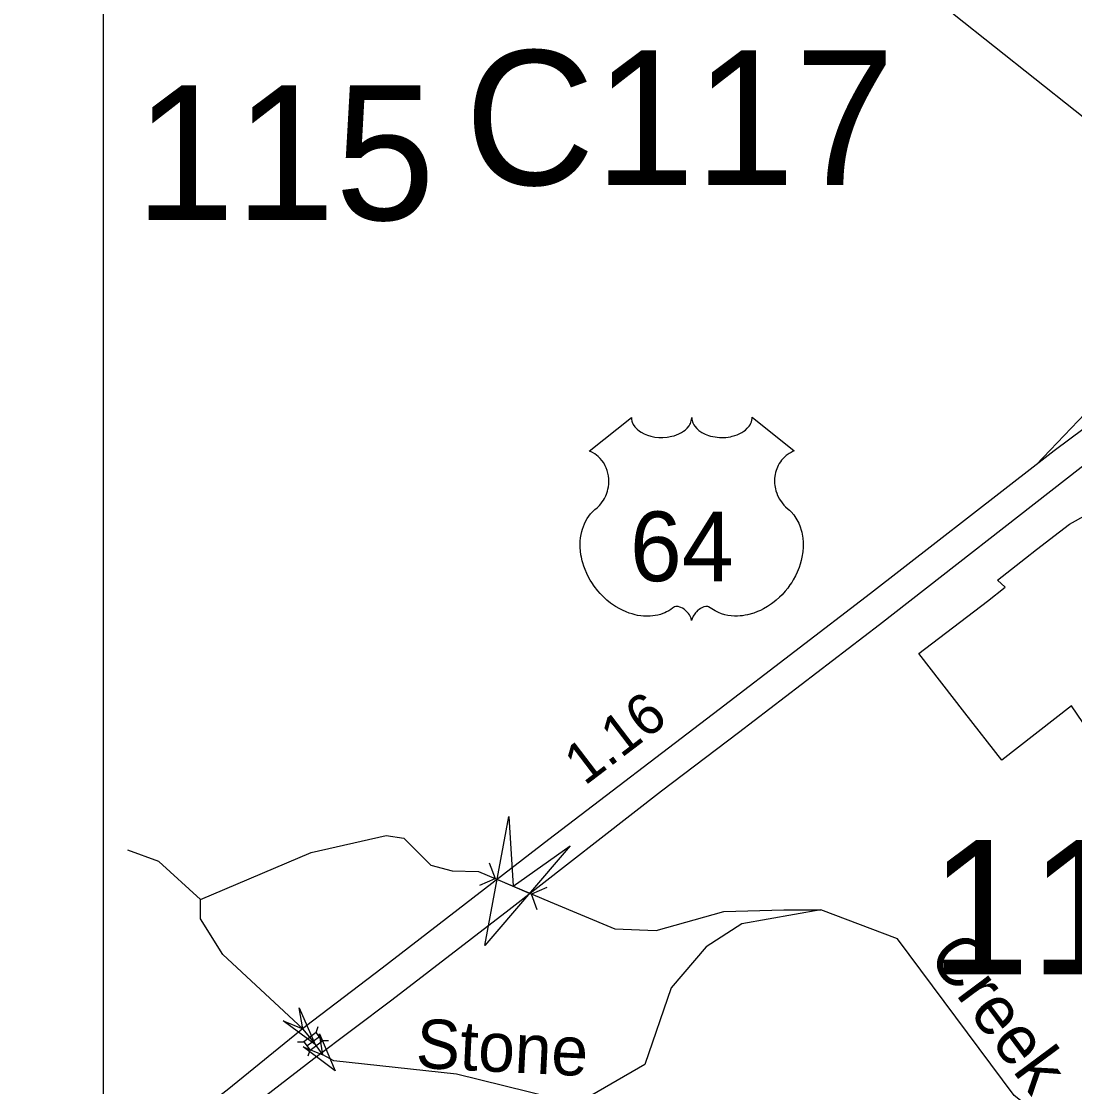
# Model space of a CAD drawing. Extents: x 2220236 to 2384410, y 720751 to 894131.
# Drawn here: x 2299383 to 2302594, y 810821 to 814069 of the extents above; entities that cross this region are included whole.
import ezdxf

# ---------------------------------------------------------------- set-up
doc = ezdxf.new("R2010")
doc.units = 0
doc.layers.add('Default', color=7, linetype='Continuous')

msp = doc.modelspace()

# ---------------------------------------------------------------- linework, layer by layer
at = {"layer": 'Default'}
for p, q in [((2300809.5, 811503.4), (2300827.1, 811455.8)), ((2300780.5, 811435.7), (2300827.1, 811455.8)), ((2300827.1, 811455.8), (2300938.2, 811408.1)), ((2300984.8, 811428.2), (2300938.2, 811408.1)), ((2300955.7, 811360.4), (2300938.2, 811408.1)), ((2300282.1, 810986.2), (2300287.7, 811004.2)), ((2300225.3, 810957.1), (2300244.2, 810957.6)), ((2300253.7, 810945), (2300291.6, 810973.6)), ((2300300.9, 810961.2), (2300319.8, 810961.8)), ((2300257.6, 810914.4), (2300263.2, 810932.4))]:
    msp.add_line(p, q, dxfattribs=at)
for points in [[(2299633.7, 818158.8), (2318694.1, 818158.8), (2318694.1, 801601.3), (2299633.7, 801601.3), (2299633.7, 818158.8)], [(2303026.8, 813458), (2302964.3, 813503.2), (2302226.3, 814089.1), (2301901.5, 814371.3), (2301400.9, 814817.8)], [(2303026.8, 813458), (2302895.1, 813248.5), (2302668.7, 812918.3), (2302476.3, 812716.3)], [(2303219, 813282), (2302940.9, 813063.9), (2302531.8, 812759.3), (2302476.3, 812716.3)], [(2300274.8, 810906.3), (2300512.6, 811085.2), (2300870.2, 811361.4), (2301334.3, 811722.6), (2301569.6, 811900.6), (2301999.5, 812230.1), (2302613.3, 812709.4), (2302643.9, 812732.1)], [(2302476.3, 812716.3), (2301971.3, 812324.1), (2301510.5, 811970.5), (2300990.8, 811574.4), (2300482.7, 811182.5), (2300249.8, 811004.5)], [(2302618.5, 811931.2), (2302584, 811982.1), (2302371.8, 811816.6), (2302259.2, 811961.1), (2302118.8, 812141.6), (2302327.8, 812301.6), (2302382.5, 812343.6), (2302358.5, 812364.8), (2302444.5, 812432), (2302478, 812458.2), (2302547.5, 812512.8), (2302577.8, 812536.4), (2302718, 812613.9)], [(2302618.5, 811931.2), (2302584, 811982.1), (2302371.8, 811816.6), (2302259.2, 811961.1), (2302118.8, 812141.6), (2302327.8, 812301.6), (2302382.5, 812343.6), (2302358.5, 812364.8), (2302444.5, 812432), (2302478, 812458.2), (2302547.5, 812512.8), (2302577.8, 812536.4), (2302718, 812613.9)], [(2299929.2, 811391.2), (2300267, 811535.2), (2300495.3, 811586.2), (2300548.7, 811578.9), (2300631.3, 811496.3), (2300696.9, 811479.3), (2300777, 811476.9), (2300882.6, 811431.9), (2300995.6, 811384.6), (2301192.2, 811301.9), (2301318.5, 811297.1), (2301524.9, 811355.4), (2301707.1, 811360.3), (2301820.2, 811360.3)], [(2302669.3, 810587.6), (2302409.3, 810793.6), (2302054.4, 811271.4), (2301820.2, 811360.3), (2301579.3, 811317.6), (2301471.2, 811247.6), (2301364.4, 811121.7), (2301283.4, 810888.7), (2301076.3, 810768.7), (2300709.2, 810858.7), (2300335.8, 810899.8), (2300302.4, 810917.4), (2300272.6, 810959.3), (2300241.1, 810997), (2299997.3, 811223.4), (2299929.2, 811332.2), (2299929.2, 811391.2), (2299802.3, 811507.5), (2299708.3, 811541.5)], [(2300249.8, 811004.5), (2300010.3, 810810.6), (2299383.2, 810331.2)], [(2299997.6, 810692.7), (2300046.9, 810730.7), (2300274.8, 810906.3)]]:
    msp.add_lwpolyline(points, dxfattribs=at)
for points in [[(2301242.7, 812861.4), (2301243, 812856), (2301244.3, 812849.7), (2301245.3, 812846.5), (2301248.2, 812840.2), (2301253.1, 812832.8), (2301259.9, 812825.6), (2301267.6, 812819.3), (2301272.7, 812816), (2301281.5, 812811.3), (2301291.5, 812807.1), (2301302.5, 812803.9), (2301313.9, 812801.6), (2301326.2, 812800.3), (2301338.5, 812800), (2301351.7, 812801), (2301366.3, 812803.8), (2301373, 812805.6), (2301380.5, 812808.2), (2301387.5, 812811), (2301395.2, 812815.1), (2301401.4, 812819.1), (2301406.2, 812822.6), (2301413, 812829.1), (2301418.4, 812835.9), (2301420.7, 812839.7), (2301422.7, 812843.3), (2301425.4, 812851.1), (2301426.2, 812854.5), (2301426.7, 812861.6), (2301427.1, 812855.6), (2301427.7, 812851.9), (2301428.7, 812848.3), (2301430.3, 812844.4), (2301433, 812838.9), (2301436, 812834.4), (2301441.8, 812827.6), (2301445.3, 812824.3), (2301448.6, 812821.6), (2301457.3, 812815.6), (2301467.5, 812810.4), (2301472.6, 812808.2), (2301477.7, 812806.4), (2301484.3, 812804.4), (2301491, 812802.8), (2301497.7, 812801.7), (2301504.5, 812800.7), (2301511.5, 812800.2), (2301517.2, 812800), (2301524.2, 812800.1), (2301530.7, 812800.5), (2301537.3, 812801.2), (2301544.6, 812802.5), (2301550.4, 812803.7), (2301558.2, 812805.8), (2301565.1, 812808.3), (2301571.3, 812811), (2301579.3, 812815.1), (2301585.7, 812819.2), (2301590.4, 812823), (2301596.1, 812828.1), (2301601.4, 812834.3), (2301604.5, 812838.8), (2301606.7, 812843.4), (2301608.7, 812848.3), (2301610, 812853.4), (2301610.6, 812857.9), (2301610.7, 812861.8), (2301739.3, 812759.3), (2301736.3, 812758.2), (2301729.3, 812754.7), (2301723.8, 812751.5), (2301714.9, 812745.2), (2301711.1, 812741.8), (2301707.3, 812738.2), (2301703.8, 812734.4), (2301700.7, 812730.9), (2301697, 812725.7), (2301693.7, 812720.5), (2301690.4, 812714.8), (2301688, 812709.9), (2301684.1, 812699.6), (2301682.2, 812693), (2301681, 812687.5), (2301679.4, 812676), (2301679.1, 812670.5), (2301679.1, 812665.1), (2301679.4, 812659.4), (2301679.9, 812654), (2301680.9, 812648.3), (2301681.8, 812643.3), (2301683.4, 812637.1), (2301685.7, 812630), (2301688.5, 812623), (2301694.4, 812611.9), (2301701.9, 812600.5), (2301707.3, 812594.1), (2301712.6, 812588.6), (2301720.6, 812581.9), (2301724.9, 812578.1), (2301729.8, 812573.2), (2301737.8, 812563.9), (2301741.1, 812559.4), (2301744.4, 812554.5), (2301747.4, 812549.4), (2301750.5, 812543.9), (2301752.9, 812539.2), (2301757.4, 812528.1), (2301760.7, 812517.4), (2301762.3, 812511.8), (2301764.6, 812499.2), (2301765.6, 812493), (2301766.5, 812480.6), (2301766.6, 812465.8), (2301765.4, 812451.6), (2301762.8, 812435.1), (2301760.6, 812425.3), (2301757.2, 812413.8), (2301753.9, 812403.8), (2301748.1, 812389.2), (2301742.9, 812378.5), (2301736.1, 812366.1), (2301731.5, 812358.5), (2301726.1, 812350.5), (2301719.3, 812341.2), (2301711.4, 812331.3), (2301701.9, 812320.9), (2301694.2, 812313.2), (2301684.2, 812304.3), (2301678.1, 812299.3), (2301669.5, 812292.7), (2301657.6, 812284.8), (2301645.9, 812278.1), (2301636, 812273), (2301627.2, 812269.2), (2301615.8, 812264.8), (2301596.8, 812259.6), (2301589.9, 812258.2), (2301581.7, 812256.9), (2301574, 812256.2), (2301566.6, 812255.7), (2301556.6, 812255.7), (2301546.6, 812256.5), (2301537.2, 812257.9), (2301527.4, 812259.9), (2301517.1, 812262.9), (2301507.8, 812266.6), (2301498.4, 812271.2), (2301482.5, 812281.3), (2301477.9, 812283.7), (2301475.3, 812284.4), (2301469.2, 812284.7), (2301463.4, 812283.5), (2301457.5, 812281.1), (2301453.9, 812279.2), (2301449.2, 812276.1), (2301445.5, 812273.2), (2301441.1, 812269), (2301438.1, 812265.5), (2301435.8, 812262.8), (2301431.3, 812255.7), (2301429.7, 812252.4), (2301428, 812248.1), (2301426.5, 812241.7), (2301424.5, 812249.7), (2301422.2, 812255), (2301419.4, 812259.6), (2301416.6, 812263.6), (2301412.1, 812268.8), (2301408.1, 812272.7), (2301403.2, 812276.6), (2301398.1, 812279.7), (2301393.9, 812281.9), (2301390.1, 812283.3), (2301385.5, 812284.4), (2301381.7, 812284.8), (2301378.6, 812284.7), (2301374.3, 812283.7), (2301368.5, 812279.5), (2301363, 812275.7), (2301357, 812272), (2301349.8, 812268.2), (2301344.6, 812265.8), (2301338.4, 812263.3), (2301331.1, 812260.9), (2301323.2, 812258.8), (2301315, 812257.2), (2301307.9, 812256.1), (2301300.2, 812255.4), (2301293.3, 812255.2), (2301286.1, 812255.3), (2301279.3, 812255.8), (2301271.5, 812256.5), (2301261.8, 812257.9), (2301253.8, 812259.8), (2301245.2, 812262), (2301236.5, 812264.8), (2301227.2, 812268.3), (2301215.5, 812273.4), (2301207.4, 812277.6), (2301194.5, 812285), (2301179.5, 812295.4), (2301168.1, 812304.6), (2301159.8, 812312.1), (2301147.6, 812324.6), (2301140.4, 812332.7), (2301129.1, 812347.3), (2301121.9, 812357.9), (2301117.2, 812365.6), (2301110.4, 812378.1), (2301106.6, 812385.9), (2301101.8, 812397.3), (2301098, 812407.7), (2301094.8, 812417.6), (2301093.1, 812423.9), (2301090.6, 812434.9), (2301089.1, 812442.7), (2301087.7, 812453.4), (2301086.9, 812464.8), (2301086.7, 812475.2), (2301087, 812483.8), (2301088, 812493.9), (2301089.7, 812504.7), (2301091.8, 812513.9), (2301093.6, 812520.5), (2301096.4, 812528.5), (2301100, 812537.4), (2301104.2, 812545.9), (2301108.3, 812553), (2301113.4, 812560.6), (2301118.4, 812567), (2301125, 812574.2), (2301131.8, 812580.7), (2301138.1, 812585.8), (2301145.5, 812593.1), (2301149.4, 812597.5), (2301154, 812603.7), (2301157.8, 812609.4), (2301160.7, 812614.5), (2301164.6, 812622), (2301167, 812627.6), (2301170, 812636.3), (2301171.4, 812642.3), (2301173, 812650.2), (2301173.9, 812657.5), (2301174.3, 812666.7), (2301174.1, 812674.3), (2301173.1, 812683.2), (2301171.4, 812691.7), (2301169.4, 812699.2), (2301166.2, 812707.7), (2301163.3, 812713.9), (2301158.4, 812722.4), (2301152.9, 812730.2), (2301147.2, 812736.6), (2301141.5, 812742.3), (2301136.1, 812746.5), (2301130.9, 812750.2), (2301124.3, 812754.2), (2301118, 812757.3), (2301114.1, 812758.9)], [(2301056.5, 811555.3), (2300796.3, 811251.5), (2300869.7, 811644.7), (2300882.6, 811431.9)], [(2300230.6, 811061.1), (2300278.8, 810949.1), (2300181.1, 811022), (2300241.1, 810997)], [(2300292, 810981.5), (2300340.1, 810869.5), (2300242.4, 810942.4), (2300302.4, 810917.4)], [(2300263.2, 810932.4), (2300301.1, 810961), (2300282, 810986.2), (2300244.2, 810957.6)]]:
    msp.add_lwpolyline(points, close=True, dxfattribs=at)

# ---------------------------------------------------------------- texts
for s, height, p in [('C117', 410.1, (2300734.9, 813570.1)), ('115', 410.1, (2299729.3, 813463.3)), ('64', 212.5, (2301238.4, 812362)), ('118', 410.1, (2302152.3, 811163.3))]:
    msp.add_text(s, height=height, dxfattribs=at).set_placement(p)
for s, height, rotation, p in [('1.16', 125, 37.3087, (2301100.3, 811736.5)), ('Creek', 150, 306.6127, (2302143.6, 811218.2)), ('Stone', 150, 357.1646, (2300583.8, 810878.6))]:
    msp.add_text(s, height=height, rotation=rotation, dxfattribs=at).set_placement(p)

doc.saveas('drawing.dxf')
